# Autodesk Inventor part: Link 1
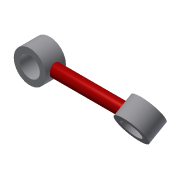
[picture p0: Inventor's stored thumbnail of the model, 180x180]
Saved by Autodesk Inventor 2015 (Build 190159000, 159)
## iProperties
Created: 2020-09
Part Number: Link 1
Material: 一般
Document SubType Name: Modeling
Designer: 徐冠倫
Mass: 0.427586 g
Surface Area: 6.79296 cm^2
Volume: 0.427586 cm^3
Density: 1 g/cm^3
Appearance: 預設
Author: IANNIAN
Title: D:\Desktop\OCW-Computer-Aided Engineering Drawing\OCW_Topic 06：組合圖與機構模擬(進階)\6-2_Inventor Studio\Banet\Banet(STP)\Part1.stp
Creation Date: 2020-09-04
Sending System: Autodesk Inventor 2020
Preprocessor: ST-DEVELOPER v18
Author: 徐冠倫
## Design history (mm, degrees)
node "Part11"
body "Solid1"
node "Base1"
